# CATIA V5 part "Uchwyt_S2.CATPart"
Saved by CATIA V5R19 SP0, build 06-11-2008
Part number: Uchwyt
Bounding box of the stored display mesh (mm): x -79 to 79, y -80 to 79, z 0 to 116
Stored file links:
  G:\Catia\CD\Ustawienia\Uchwyt\Uchwyt_S2.CATPart
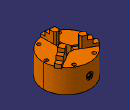
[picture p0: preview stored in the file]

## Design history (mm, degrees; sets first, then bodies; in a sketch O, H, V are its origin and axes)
Parameters
  Rozstaw = 30 mm
Body1 (main body)
  Sketch1 on xy-plane, origin (0, 0, 0), H (1, 0, 0), V (0, 1, 0)
    circle A1 centre (0, 0) radius 79
    circle A2 centre (0, 0) radius 16
    radius A1 = 79
    radius A2 = 16
  Pad1: profile Sketch1, direction (0, 0, 1), length 80
  Sketch2 on end face of Pad1, origin (55.5929, -45.085, 80), H (1, 0, 0), V (0, 1, 0)
    point P1 (-21.2096, -14.6017)
    construction line L1 (-55.5929, 134.677) -> (-55.5929, -51.2454)
    reference intersected line E1 through (-55.5929, 0) direction (0, 1) from yz-plane
    construction line L2 (-55.5929, 44.9521) -> (-10.3181, -33.4663)
    point P4 (-55.5929, 44.9521)
    angle L2 L1 = 30
    vertical: L1 V
    coincidence: E1 L1, P4 L1, P1 L2
  Hole1: placed by Sketch2, at (34.3834, -59.6867, 80) direction (0, 0, -1), diameter 8, through (limit type 6), counterbore diameter 12, counterbore depth 10
  CircPattern1: of Hole1, instances 6, angular step 60 {= 360.0*1 deg/CircPattern1.AngularNumber}, axis from end face of Pad1
  Sketch3 on end face of Pad1, origin (0, 0, 80), H (1, 0, 0), V (0, 1, 0)
    line L1 (-9, -8.5652) -> (9, -8.5652)
    line L2 (9, -8.5652) -> (9, -94.3558)
    line L3 (9, -94.3558) -> (-9, -94.3558)
    line L4 (-9, -94.3558) -> (-9, -8.5652)
    distance L4 L2 = 18
    distance L2 V = 9
    horizontal: L1 H, L3 H
    vertical: L2 V, L4 V
  Pocket1: profile Sketch3, direction (0, 0, -1), length 4
  CircPattern2: of Pocket1, instances 3, angular step 120 {= 360.0*1 deg/CircPattern2.AngularNumber}, axis from end face of Pad1
  Plane1: type Offset, Offset 79, RefPlane zx-plane
  Sketch4 on Plane1, origin (0, 79, 0), H (-1, 0, 0), V (0, 0, 1)
    circle A1 centre (0, 40) radius 8
    point P1 (0, 40)
    reference projected line E1 through (0, 0) direction (0, 1) from axis of face of Pad1 from Sketch1.A1
    distance A1 E1 = 8
    coincidence: P1 V
  Pocket2: profile Sketch4, direction (0, -1, 0), length 3
  Sketch5 on Plane1, origin (0, 79, 0), H (-1, 0, 0), V (0, 0, 1)
    circle A1 centre (0, 40) radius 12
    point P1 (0, 40)
    reference projected line E1 through (0, 0) direction (0, 1) from axis of face of Pad1 from Sketch1.A1
    distance A1 E1 = 12
    coincidence: P1 V
  Pocket3: profile Sketch5, direction (0, -1, 0), length 2
  Sketch6 on end face of Pocket2, origin (0, 76, 0), H (-1, 0, 0), V (0, 0, 1)
    point P1 (0, 40)
    point P2 (-4.348, 34.4178)
    point P3 (2.6603, 33.4434)
    point P4 (7.0083, 39.0256)
    point P5 (4.348, 45.5822)
    point P6 (-2.6603, 46.5566)
    point P7 (-7.0083, 40.9744)
    point P8 (-0.8438, 33.9306)
    line L1 (-4.348, 34.4178) -> (2.6603, 33.4434)
    line L2 (2.6603, 33.4434) -> (7.0083, 39.0256)
    line L3 (7.0083, 39.0256) -> (4.348, 45.5822)
    line L4 (4.348, 45.5822) -> (-2.6603, 46.5566)
    line L5 (-2.6603, 46.5566) -> (-7.0083, 40.9744)
    line L6 (-7.0083, 40.9744) -> (-4.348, 34.4178)
    construction line L7 (0, 40) -> (-0.8438, 33.9306)
    construction circle A1 centre (0, 40) radius 7.0758
    construction arc A2 centre (-2.6603, 46.5566) radius 7.0758 from (4.348, 45.5822) to (-7.0083, 40.9744) cw
    construction arc A3 centre (2.6603, 33.4434) radius 7.0758 from (7.0083, 39.0256) to (-4.348, 34.4178) ccw
    coincidence: P1 V, A1 P2, A1 P3, A1 P4, A1 P5, A1 P6, A1 P7, A2 P1, A3 P1
    midpoint: P8 L1
    parallelism: L1 L4
  Pocket4: profile Sketch6, direction (0, -1, 0), length 3
Body2
  Sketch7 on face of CircPattern2, origin (0, 0, 76), H (1, 0, 0), V (0, 1, 0)
    line L1 (-3.3431, -30) -> (3.3431, -30)
    line L2 (9, -35.6569) -> (9, -79.3004)
    line L3 (-9, -79.3004) -> (-9, -35.6569)
    point P1 (9, -75.6569)
    point P2 (-9, -75.6569)
    line L4 (-3.3431, -30) -> (-9, -35.6569)
    line L5 (3.3431, -30) -> (9, -35.6569)
    arc A1 centre (0, -21.7581) radius 58.2419 from (-9, -79.3004) to (9, -79.3004) ccw
    point P7 (0, -21.7581)
    angle L1 L4 = 45
    length L4 = 8
    angle L1 L5 = 45
    length L5 = 8
    distance P1 P2 = 18
    distance H L1 = 30 {= Rozstaw}
    distance A1 L1 = 50
    horizontal: L1 H
    vertical: L2 V, L3 V
    coincidence: L3, P7 V
  Pad2: profile Sketch7, direction (0, 0, 1), length 40
  Sketch8 on end face of Pad2, origin (0, 0, 116), H (1, 0, 0), V (0, 1, 0)
    arc A1 centre (0, 15) radius 65 from (-20.7552, -46.5973) to (37.7409, -37.921) ccw
    point P1 (0, 15)
    line L1 (37.7409, -37.921) -> (29.7667, -85.8266)
    arc A2 centre (-1.9378, -80.5492) radius 32.1407 from (29.7667, -85.8266) to (-33.6423, -85.8266) cw
    arc A3 centre (10.2629, -78.5184) radius 44.5093 from (-33.6423, -85.8266) to (-20.7552, -46.5973) cw
    reference projected line E1 (3.3431, -30) -> (-3.3431, -30) from edge [face of Pad2 from Sketch7.L1 | end face of Pad2]
    radius A1 = 65
    distance A1 E1 = 20
    coincidence: P1 V
    tangency: A2 L1, A3 A2
  Pocket5: profile Sketch8, direction (0, 0, -1), length 13.5
  Sketch9 on end face of Pocket5, origin (0, 0, 102.5), H (1, 0, 0), V (0, 1, 0)
    arc A1 centre (0, 0) radius 65 from (-20.7552, -61.5973) to (37.7409, -52.921) ccw
    reference projected line E1 (3.3431, -30) -> (-3.3431, -30) from edge [face of Pad2 from Sketch7.L1 | end face of Pad2]
    line L1 (37.7409, -52.921) -> (30.2023, -95.7126)
    line L2 (30.2023, -95.7126) -> (-20.7552, -95.7126)
    line L3 (-20.7552, -95.7126) -> (-20.7552, -61.5973)
    distance A1 E1 = 35
    horizontal: L2 H
    vertical: L3 V
  Pocket6: profile Sketch9, direction (0, 0, -1), length 13.5
  CircPattern3: of the body so far, instances 3, angular step 120, axis from face of Pad1 from Sketch1.A2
